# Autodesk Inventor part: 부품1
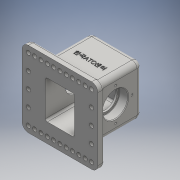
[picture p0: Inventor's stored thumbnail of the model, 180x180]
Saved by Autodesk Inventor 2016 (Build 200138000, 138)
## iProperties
Created: 2018-11
Part Number: 부품1
Material: Generic
Document SubType Name: Modeling
Designer: Administrator
Density: 1 g/cm^3
Appearance: Default
Author: Administrator
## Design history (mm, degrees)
sketch "스케치2"
  geometry: L1 (40, 40)-(-40, 40); L2 (-40, 40)-(-40, -40); L3 (-40, -40)-(40, -40); L4 (40, -40)-(40, 40); L5 (40, 40)-(-40, -40); L6 (-40, 40)-(40, -40); 1 further point
  constraints: 12 end point, 2 midpoint, 2 parallel, 1 horizontal, 1 perpendicular
  dimensions: "d0" = 80 distance of L3.end L2.end; "d1" = 80 distance of L2.end L1.end
extrude "돌출1" new body sketch "스케치2" distance "d2" = 80; taper "d3" = 0 deg
sketch "스케치3"
  geometry: L1 (-60, -60)-(60, -60); L2 (60, -60)-(60, 60); L3 (60, 60)-(-60, 60); L4 (-60, 60)-(-60, -60); L5 (-60, -60)-(60, 60); L6 (60, -60)-(-60, 60); 1 further point
  constraints: 12 end point, 2 midpoint, 2 parallel, 1 horizontal, 1 perpendicular
  dimensions: "d4" = 120 distance between parallel lines of L2 L4; "d5" = 120 distance between parallel lines of L1 L3
extrude "돌출2" join sketch "스케치3" distance "d6" = 10; taper "d7" = 0 deg
sketch "스케치5"
  geometry: L1 (-23, -30)-(23, -30); L2 (23, -30)-(23, 30); L3 (23, 30)-(-23, 30); L4 (-23, 30)-(-23, -30); L5 (-23, -30)-(23, 30); L6 (23, -30)-(-23, 30); 1 further point
  constraints: 12 end point, 2 midpoint, 2 parallel, 1 horizontal, 1 perpendicular
  dimensions: "d8" = 46 distance of L3.end L2.end; "d10" = 60 distance between parallel lines of L1 L3
extrude "돌출3" cut sketch "스케치5" distance "d11" = 80; taper "d12" = 0 deg
sketch "스케치6"
  geometry: L1 (100, -90)-(-20, -90) reference; C1 r 20 at (40, -42); 1 further point
  constraints: 1 centre point
  dimensions: "d13" = 40 diameter of C1; "d14" = 48 distance from line of L1 C1.centre
extrude "돌출4" cut sketch "스케치6" distance "d15" = 14; taper "d16" = 0 deg
sketch "스케치7"
  geometry: C1 r 16.5 at (0, 0); 1 further point
  constraints: 1 centre point
  dimensions: "d17" = 33 diameter of C1
extrude "돌출5" cut sketch "스케치7" distance "d18" = 3; taper "d19" = 0 deg
sketch "스케치8"
  geometry: L1 (100, -90)-(-20, -90) reference; C1 r 20 at (40, -42); 1 further point
  constraints: 1 centre point
  dimensions: "d20" = 40 diameter of C1; "d21" = 48 distance from line of L1 C1.centre
extrude "돌출6" cut sketch "스케치8" distance "d22" = 14; taper "d23" = 0 deg
sketch "스케치9"
  geometry: C1 r 16.5 at (0, 0); 1 further point
  constraints: 1 centre point
  dimensions: "d24" = 33 diameter of C1
extrude "돌출7" cut sketch "스케치9" distance "d25" = 3; taper "d26" = 0 deg
sketch "스케치10"
  geometry: C1 r 7.5 at (0, 0); 1 further point
  constraints: 1 centre point, 1 coincident
  dimensions: "d27" = 15 diameter of C1
extrude "돌출8" join sketch "스케치10" distance "d28" = 5; taper "d29" = 0 deg
hole "구멍1" diameter "d32" = 4.917; stored, may be unused: countersink angle "d36" = 90 deg, drill point angle "d38" = 0 deg; dims "d30" = 10, "d31" = 10, "d33" = 12, "d34" = 4, "d35" = 2, "d37" = 60.85
fillet "모깎기1" dims "d39" = 8
sketch "스케치12"
  geometry: 29 further points
  dimensions: "d40" = 50 distance of point (0, 50) point (0, 0); "d41" = 50 distance of point (0, -50) point (0, 0); "d42" = 50 distance of point (-50, 0) point (0, 0); "d43" = 50 distance of point (50, 0) point (0, 0); "d44" = 10 distance of point (0, 50) point (10, 50); "d45" = 10 distance of point (20, 50) point (10, 50); "d46" = 10 distance of point (30, 50) point (20, 50); "d47" = 10 distance of point (40, 50) point (30, 50); "d48" = 10 distance of point (50, 50) point (40, 50); "d49" = 10 distance of point (-10, 50) point (0, 50); "d50" = 10 distance of point (-20, 50) point (-10, 50); "d51" = 10 distance of point (-40, 50) point (-30, 50); "d52" = 10 distance of point (-30, 50) point (-20, 50); "d53" = 10 distance of point (-50, 50) point (-40, 50); "d54" = 25 distance of point (-50, 25) point (-50, 50); "d55" = 25 distance of point (-50, 0) point (-50, 25); "d56" = 25 distance of point (-50, -25) point (-50, 0); "d57" = 25 distance of point (-50, -50) point (-50, -25); "d58" = 10 distance of point (-40, -50) point (-50, -50); "d59" = 10 distance of point (-30, -50) point (-40, -50); "d60" = 10 distance of point (-20, -50) point (-30, -50); "d61" = 10 distance of point (-10, -50) point (-20, -50); "d62" = 10 distance of point (0, -50) point (-10, -50); "d63" = 10 distance of point (0, -50) point (10, -50); "d64" = 10 distance of point (20, -50) point (10, -50); "d65" = 10 distance of point (20, -50) point (30, -50); "d66" = 10 distance of point (30, -50) point (40, -50); "d67" = 10 distance of point (40, -50) point (50, -50); "d68" = 25 distance of point (50, 25) point (50, 50); "d69" = 25 distance of point (50, 0) point (50, -25)
hole "구멍2" sketch "스케치12" diameter "d70" = 6.6; stored, may be unused: countersink angle "d74" = 90 deg, drill point angle "d76" = 0 deg; dims "d71" = 12, "d72" = 4, "d73" = 2, "d75" = 60.85
fillet "모깎기2" dims "d77" = 10
fillet "모깎기3" dims "d78" = 3
fillet "모깎기4" dims "d79" = 3
fillet "모깎기5" dims "d80" = 3
chamfer "모따기1" distance "d81" = 1; stored, may be unused: second distance "d82" = 2, angle "d83" = 45 deg
sketch "스케치13"
  geometry: L1 (82, -82)-(-18, -82) reference; A1 r 26 centre (32, -34) between (32, -8) and (6, -34); 3 further points
  constraints: 4 point on circle, 1 centre point
  dimensions: "d84" = 52 diameter of A1; "d85" = 48 distance from line of L1 A1.centre
hole "구멍3" sketch "스케치13" at (32, -8), (6, -34), (32, -60), (58, -34) diameter "d86" = 3.242; stored, may be unused: countersink angle "d90" = 90 deg, drill point angle "d92" = 118 deg; dims "d87" = 8, "d88" = 4, "d89" = 2, "d91" = 10
fillet "모깎기6" dims "d93" = 0.6
sketch "스케치16"
  geometry: L1 (82, -82)-(-18, -82) reference; 3 further points
  constraints: 1 midpoint, 1 vertical alignment, 1 other
  dimensions: "d94" = 48 distance from line of L1 point (32, -34)
feature "엠보싱1" sketch "스케치16" dims "d0" = 80, "d1" = 80, "d8" = 46, "d10" = 60, "d95" = 0.5, "d96" = 0
node "솔리드1"
mirror "대칭1"
